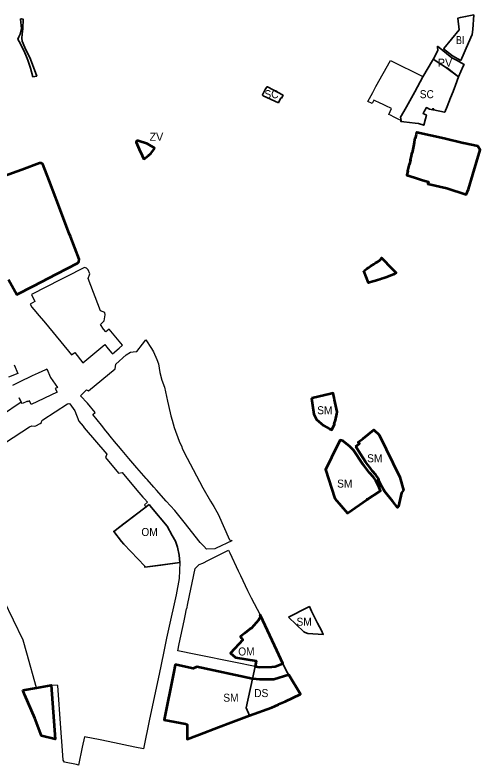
# Model space of a CAD drawing. Extents: x -650276 to -642489, y -1074311 to -1066658.
# Drawn here: x -647428 to -646731, y -1071572 to -1070448 of the extents above; entities that cross this region are included whole.
import ezdxf

# ---------------------------------------------------------------- set-up
doc = ezdxf.new("R2010")
doc.units = 0
doc.header["$LTSCALE"] = 4.8
doc.header["$PDMODE"] = 32
doc.header["$PDSIZE"] = 2.4
for name, color, linetype, lineweight in [('12', 7, 'Continuous', 35), ('15', 7, 'Continuous', 35), ('17', 7, 'Continuous', 35), ('18', 7, 'Continuous', 35), ('2', 7, 'Continuous', 35), ('24', 7, 'Continuous', 35), ('40', 7, 'Continuous', 35), ('60', 7, 'Continuous', 53), ('61', 7, 'Continuous', 25)]:
    doc.layers.add(name, color=color, linetype=linetype, lineweight=lineweight)
doc.layers.add('62', color=7, linetype='Continuous')
doc.layers.add('63', color=7, linetype='Continuous')

msp = doc.modelspace()

# ---------------------------------------------------------------- linework, layer by layer
at = {"layer": '12'}
for points in [[(-647226.895, -1071181.511), (-647280.14, -1071221.92), (-647268.52, -1071236.78), (-647265.15, -1071241.1), (-647233.34, -1071274.07), (-647233.64, -1071275.42), (-647218.75, -1071273.32), (-647181.12, -1071268.66), (-647181.99, -1071257.66), (-647184.58, -1071245.67), (-647187.68, -1071236.74), (-647192.29, -1071228.1), (-647199.82, -1071213.98), (-647223.46, -1071185.83)], [(-647056.48, -1071355.32), (-647060.6, -1071346.87), (-647060.22, -1071349.87), (-647061.4, -1071352.51), (-647062.78, -1071354.77), (-647073.68, -1071366.75), (-647075.25, -1071368.01), (-647083.48, -1071374.62), (-647090.04, -1071379.44), (-647088.57, -1071381.97), (-647086.45, -1071384.59), (-647105.2, -1071404.54), (-647097.5, -1071410.96), (-647066.35, -1071415.79), (-647068.162, -1071424.298), (-647061.23, -1071425.434), (-647043.137, -1071424.978), (-647038.119, -1071424.37), (-647026.472, -1071419.614), (-647035.47, -1071400.31)]]:
    msp.add_lwpolyline(points, close=True, dxfattribs=at)
at = {"layer": '15'}
msp.add_lwpolyline([(-647404.96, -1070527.57), (-647401.35, -1070540.59), (-647395.75, -1070539.47), (-647404.879, -1070514.114), (-647413.552, -1070496.671), (-647417.297, -1070487.185), (-647418.038, -1070482.516), (-647417.482, -1070476.846), (-647416.37, -1070468.064), (-647416.148, -1070454.055), (-647418.49, -1070453.76), (-647420.13, -1070454.78), (-647420.22, -1070454.02), (-647418.41, -1070468.21), (-647420.74, -1070476.57), (-647422.285, -1070480.931), (-647424.226, -1070484.029), (-647422.19, -1070487.75), (-647414.6, -1070502.16), (-647410.86, -1070510.68), (-647408.82, -1070515.49)], close=True, dxfattribs=at)
for points in [[(-646794.59, -1070494.62), (-646794.53, -1070495.7), (-646793.75, -1070501.26), (-646800.6, -1070513.43), (-646800.94, -1070514.04)], [(-646755.84, -1070524.5), (-646754.52, -1070522.08), (-646765.96, -1070515.75), (-646770.95, -1070512.94), (-646773, -1070511.96), (-646794.59, -1070494.62)], [(-646800.94, -1070514.04), (-646788, -1070522.49), (-646782.63, -1070526.02)], [(-646782.63, -1070526.02), (-646779.68, -1070527.87), (-646762.71, -1070540.85), (-646755.84, -1070524.5)], [(-647072.11, -1071442.6), (-647060.812, -1071444.006), (-647040.089, -1071443.76), (-647017.7, -1071436.79), (-647020.52, -1071432.42), (-647026.472, -1071419.614)], [(-647068.162, -1071424.298), (-647068.162, -1071424.298), (-647072.11, -1071442.6)], [(-647026.472, -1071419.614), (-647038.119, -1071424.37), (-647043.137, -1071424.978), (-647061.23, -1071425.434), (-647068.162, -1071424.298)]]:
    msp.add_lwpolyline(points, dxfattribs=at)
msp.add_point((-647072.11, -1071442.6), dxfattribs=at)
at = {"layer": '17'}
for points in [[(-646802.19, -1070516.26), (-646816.42, -1070540.49), (-646828.45, -1070562.89), (-646841.16, -1070585.79), (-646844.76, -1070592.54), (-646849.72, -1070600.98), (-646848.99, -1070606.28), (-646849.59, -1070607.4), (-646844.96, -1070607.98), (-646827.88, -1070610.12), (-646822.99, -1070610.51), (-646815.05, -1070613.14), (-646812.5, -1070603.78), (-646811.5, -1070600.29), (-646810.82, -1070598.23), (-646816.11, -1070595.8), (-646814.52, -1070592.78), (-646811.06, -1070586.67), (-646806.41, -1070589), (-646802.06, -1070589.93), (-646801.73, -1070588.37), (-646800.13, -1070588.71), (-646800.47, -1070590.28), (-646784.18, -1070593.76), (-646784, -1070593.34), (-646783.59, -1070593.52), (-646779.9, -1070584.92), (-646774.91, -1070571.88), (-646771.17, -1070562.7), (-646767.63, -1070553.09), (-646762.71, -1070540.85), (-646782.63, -1070526.02), (-646788, -1070522.49), (-646800.94, -1070514.04)], [(-647033.01, -1070579.83), (-647029.44, -1070572.13), (-647028.52, -1070572.63), (-647026.14, -1070568.26), (-647049.52, -1070555.64), (-647050.37, -1070555.74), (-647051.14, -1070556.59), (-647052.77, -1070559.7), (-647056.79, -1070567.41), (-647056.8, -1070568.32), (-647055.79, -1070569.07)]]:
    msp.add_lwpolyline(points, close=True, dxfattribs=at)
at = {"layer": '18'}
for points in [[(-646983.66, -1071022.3), (-646982.08, -1071032.76), (-646979.75, -1071046.19), (-646976.03, -1071054.29), (-646965.69, -1071063.05), (-646956.66, -1071067.91), (-646952.75, -1071069.62), (-646948.83, -1071061.12), (-646949.48, -1071060.79), (-646947.41, -1071054.95), (-646945.38, -1071045.82), (-646944.88, -1071042.78), (-646948.89, -1071024.84), (-646949.39, -1071021.83), (-646951.06, -1071014.78), (-646955.09, -1071015.67)], [(-646881.89, -1071077.03), (-646890.12, -1071069.67), (-646913.49, -1071088.22), (-646911.58, -1071089.9), (-646917.04, -1071094.75), (-646910.53, -1071105.18), (-646902.62, -1071117.58), (-646895.56, -1071126.84), (-646892.339, -1071131.481), (-646886.78, -1071137.25), (-646882.37, -1071143.39), (-646883.63, -1071144.15), (-646873.89, -1071161.58), (-646861.58, -1071177.05), (-646854.49, -1071185.87), (-646852.86, -1071183.98), (-646848.58, -1071163.95), (-646845.39, -1071159.98), (-646850.93, -1071140.54)], [(-646951.831, -1071107.765), (-646955.138, -1071114.466), (-646962.471, -1071129.325), (-646948.286, -1071172.534), (-646929.64, -1071194.58), (-646899.85, -1071173.89), (-646881.68, -1071161.83), (-646879.91, -1071161.24), (-646881.97, -1071155.84), (-646887.07, -1071145.66), (-646890.59, -1071140.39), (-646896.62, -1071133.93), (-646904.64, -1071123.54), (-646906.72, -1071120.46), (-646920.54, -1071099.98), (-646925.88, -1071094.68), (-646936.51, -1071086.33), (-646940.67, -1071085.15), (-646940.67, -1071085.15)], [(-647017.93, -1071350.33), (-647013.15, -1071348.01), (-647004.02, -1071343.32), (-647003.37, -1071342.99), (-646993.38, -1071337.85), (-646986.69, -1071334.53), (-646983.33, -1071341.44), (-646977.95, -1071352.38), (-646974.28, -1071359.48), (-646968.63, -1071370.46), (-646965.74, -1071376.18), (-646988.77, -1071374.77), (-646992.95, -1071373.61), (-646994.85, -1071372.49)], [(-647072.11, -1071442.6), (-647155.36, -1071425), (-647161.2, -1071427.33), (-647185.99, -1071421.98), (-647187.85, -1071421.58), (-647190.4, -1071434.75), (-647204.42, -1071504.1), (-647172.74, -1071510.15), (-647170.01, -1071511.22), (-647170.18, -1071532.22), (-647170.23, -1071533.44), (-647155.58, -1071527.62), (-647151.28, -1071525.99), (-647123.17, -1071515.01), (-647104.47, -1071508.08), (-647076.46, -1071497.69), (-647081.488, -1071486.251)]]:
    msp.add_lwpolyline(points, close=True, dxfattribs=at)
msp.add_point((-646899.85, -1071173.89), dxfattribs=at)
at = {"layer": '2'}
for points in [[(-646739.74, -1070447.98), (-646752.29, -1070450.28), (-646760.03, -1070451.56), (-646763.94, -1070452.95), (-646761.8, -1070470.4), (-646785.15, -1070498.05), (-646785.5, -1070498.47)], [(-646759.42, -1070516.37), (-646747.89, -1070489.87), (-646742.37, -1070477.2), (-646741.33, -1070469.79), (-646739.74, -1070447.98)], [(-646785.5, -1070498.47), (-646771.9, -1070509.4), (-646759.42, -1070516.37)]]:
    msp.add_lwpolyline(points, dxfattribs=at)
at = {"layer": '24'}
msp.add_line((-647081.488, -1071486.251), (-647076.46, -1071497.69), dxfattribs=at)
for points in [[(-647017.7, -1071436.79), (-647040.089, -1071443.76), (-647060.812, -1071444.006), (-647072.11, -1071442.6), (-647081.488, -1071486.251)], [(-647076.46, -1071497.69), (-647042.78, -1071485.76), (-647022.81, -1071476.61), (-646999.77, -1071465.81), (-647017.7, -1071436.79)]]:
    msp.add_lwpolyline(points, dxfattribs=at)
at = {"layer": '40'}
for points in [[(-647218.44, -1070647.43), (-647229.34, -1070640.91), (-647243.28, -1070636.43), (-647245.6, -1070636.4), (-647246.49, -1070638.53), (-647241.89, -1070648.94)], [(-647241.89, -1070648.94), (-647237.61, -1070658.33), (-647235.02, -1070664.1), (-647227.76, -1070658.33)], [(-647227.76, -1070658.33), (-647224.57, -1070655.48), (-647224.37, -1070655.59), (-647218.44, -1070647.43)]]:
    msp.add_lwpolyline(points, dxfattribs=at)
at = {"layer": '60'}
msp.add_line((-647235.02, -1070664.1), (-647227.76, -1070658.33), dxfattribs=at)
for points in [[(-646825.54, -1070624.03), (-646826.12, -1070623.9), (-646826.45, -1070627.3), (-646827.98, -1070632.83), (-646828.22, -1070632.77), (-646829.55, -1070638.78), (-646829.55, -1070638.78), (-646829.3, -1070638.83), (-646830.51, -1070644.3), (-646830.26, -1070644.35), (-646832.46, -1070654.31), (-646832.7, -1070654.26), (-646834.27, -1070661.39), (-646834.27, -1070661.39), (-646834.4, -1070661.35), (-646835.23, -1070665.08), (-646835.1, -1070665.12), (-646836.6, -1070671.54), (-646836.6, -1070671.54), (-646836.87, -1070671.46), (-646839.27, -1070681.62), (-646838.96, -1070681.72), (-646840.36, -1070687.86), (-646828.7, -1070691.73), (-646816.84, -1070695.43), (-646808.09, -1070698.19), (-646808.76, -1070701.11), (-646780.44, -1070707.59), (-646751.23, -1070717), (-646748.04, -1070709.23), (-646741.52, -1070687.22), (-646730.66, -1070650.07), (-646734.18, -1070644.6), (-646755.21, -1070639.87), (-646755.84, -1070639.88), (-646784.62, -1070633.19)], [(-646904.8, -1070831.23), (-646900.57, -1070828.42), (-646900.09, -1070828.1), (-646897.34, -1070826.28), (-646894.84, -1070824.62), (-646892.34, -1070822.96), (-646889.85, -1070821.3), (-646887.3, -1070819.61), (-646884.68, -1070817.87), (-646882.18, -1070816.21), (-646878.66, -1070812.72), (-646878.61, -1070812.14), (-646862.56, -1070828.29), (-646856.41, -1070834.13), (-646860.55, -1070836.71), (-646871.78, -1070841.33), (-646875.05, -1070842.32), (-646878.26, -1070843.29), (-646881.11, -1070844.21), (-646884.27, -1070845.17), (-646887.32, -1070846.14), (-646891.42, -1070847.44), (-646897.71, -1070849.39), (-646901.26, -1070840.31)], [(-646983.66, -1071022.3), (-646982.08, -1071032.76), (-646979.75, -1071046.19), (-646976.03, -1071054.29), (-646965.69, -1071063.05), (-646956.66, -1071067.91), (-646952.75, -1071069.62), (-646948.83, -1071061.12), (-646949.48, -1071060.79), (-646947.41, -1071054.95), (-646945.38, -1071045.82), (-646944.88, -1071042.78), (-646948.89, -1071024.84), (-646949.39, -1071021.83), (-646951.06, -1071014.78), (-646955.09, -1071015.67), (-646982.41, -1071022.23)], [(-646917.04, -1071094.75), (-646911.58, -1071089.9), (-646913.49, -1071088.22), (-646906.17, -1071082.72), (-646890.12, -1071069.67), (-646881.89, -1071077.03), (-646850.93, -1071140.54), (-646845.39, -1071159.98), (-646848.58, -1071163.95), (-646852.86, -1071183.98), (-646854.49, -1071185.87), (-646861.58, -1071177.05), (-646873.89, -1071161.58), (-646877.226, -1071155.611), (-646883.63, -1071144.15), (-646882.37, -1071143.39), (-646886.78, -1071137.25), (-646892.11, -1071131.81), (-646895.56, -1071126.84), (-646902.62, -1071117.58), (-646910.53, -1071105.18)], [(-646951.831, -1071107.765), (-646955.138, -1071114.466), (-646962.471, -1071129.325), (-646948.286, -1071172.534), (-646929.64, -1071194.58), (-646899.85, -1071173.89), (-646881.68, -1071161.83), (-646879.91, -1071161.24), (-646881.97, -1071155.84), (-646887.07, -1071145.66), (-646890.59, -1071140.39), (-646896.62, -1071133.93), (-646904.64, -1071123.54), (-646906.72, -1071120.46), (-646920.54, -1071099.98), (-646925.88, -1071094.68), (-646936.51, -1071086.33), (-646940.67, -1071085.15)], [(-647056.48, -1071355.32), (-647060.6, -1071346.87), (-647060.22, -1071349.87), (-647061.4, -1071352.51), (-647062.78, -1071354.77), (-647073.68, -1071366.75), (-647075.25, -1071368.01), (-647083.48, -1071374.62), (-647090.04, -1071379.44), (-647088.57, -1071381.97), (-647086.45, -1071384.59), (-647105.2, -1071404.54), (-647097.5, -1071410.96), (-647066.35, -1071415.79), (-647068.162, -1071424.298), (-647061.23, -1071425.434), (-647043.137, -1071424.978), (-647038.119, -1071424.37), (-647026.472, -1071419.614), (-647035.47, -1071400.31)], [(-647072.11, -1071442.6), (-647155.36, -1071425), (-647161.2, -1071427.33), (-647185.99, -1071421.98), (-647187.85, -1071421.58), (-647190.4, -1071434.75), (-647204.42, -1071504.1), (-647172.74, -1071510.15), (-647170.01, -1071511.22), (-647170.18, -1071532.22), (-647170.23, -1071533.44), (-647155.58, -1071527.62), (-647151.28, -1071525.99), (-647123.17, -1071515.01), (-647104.47, -1071508.08), (-647076.46, -1071497.69), (-647042.78, -1071485.76), (-647038.62, -1071483.74), (-647033.09, -1071481.06), (-647032.73, -1071480.88), (-647022.81, -1071476.61), (-646999.77, -1071465.81), (-647017.7, -1071436.79), (-647040.089, -1071443.76), (-647060.812, -1071444.006)], [(-647416.42, -1071460.03), (-647396.02, -1071456.32), (-647374.2, -1071452.36), (-647368.26, -1071532.99), (-647388.29, -1071528.41), (-647398.64, -1071501.96), (-647413.54, -1071467.53)]]:
    msp.add_lwpolyline(points, close=True, dxfattribs=at)
for points in [[(-647218.44, -1070647.43), (-647229.34, -1070640.91), (-647243.28, -1070636.43), (-647245.6, -1070636.4), (-647246.49, -1070638.53), (-647241.89, -1070648.94)], [(-647241.89, -1070648.94), (-647237.61, -1070658.33), (-647235.02, -1070664.1)], [(-647227.76, -1070658.33), (-647224.57, -1070655.48), (-647224.37, -1070655.59), (-647218.44, -1070647.43)], [(-647437.79, -1070844.12), (-647425.58, -1070866.7), (-647401.15, -1070854.25), (-647365.48, -1070835.85), (-647334.27, -1070819.86), (-647332.51, -1070817.97), (-647332.25, -1070813.72), (-647345.18, -1070779.89), (-647346.96, -1070775.41), (-647365.94, -1070725.08), (-647367.67, -1070720.73), (-647377.04, -1070696.22), (-647386.39, -1070671.74), (-647388.31, -1070669.95), (-647391.74, -1070670.16), (-647418.28, -1070679.89), (-647444.78, -1070689.6)]]:
    msp.add_lwpolyline(points, dxfattribs=at)
at = {"layer": '61'}
for points in [[(-646867.54, -1070597.11), (-646863.26, -1070588.3), (-646872.19, -1070583.97), (-646876.02, -1070582.12), (-646877.88, -1070581.22), (-646879.541, -1070580.417), (-646889.9, -1070575.41), (-646892.4, -1070580.64), (-646899.2, -1070577.61), (-646891.65, -1070564.15), (-646886.72, -1070555.37), (-646864.73, -1070516.2), (-646816.66, -1070540.37), (-646816.42, -1070540.49), (-646828.45, -1070562.89), (-646838.95, -1070581.53), (-646841.16, -1070585.79), (-646844.76, -1070592.54), (-646849.72, -1070600.98), (-646849.72, -1070600.98), (-646848.99, -1070606.28), (-646852.3, -1070604.63), (-646859.48, -1070601.1), (-646865.02, -1070598.34)], [(-647299.98, -1070891.49), (-647318.68, -1070842.72), (-647316.06, -1070835.75), (-647318.44, -1070829.76), (-647321.01, -1070827.14), (-647324.15, -1070826.29), (-647331.02, -1070829.74), (-647345.71, -1070837.13), (-647359.71, -1070844.27), (-647403.51, -1070866.6), (-647398.52, -1070877.49), (-647405.34, -1070881.23), (-647402.82, -1070885.66), (-647396.9, -1070892.8), (-647394.88, -1070895.23), (-647382.57, -1070910.05), (-647343.34, -1070957.27), (-647338.57, -1070953.63), (-647326.51, -1070969.42), (-647293.51, -1070942.01), (-647290.28, -1070945.89), (-647283.54, -1070954.02), (-647282.46, -1070955.31), (-647281.97, -1070955.9), (-647271.95, -1070947.47), (-647266.79, -1070942.95), (-647286.92, -1070918.59), (-647292.14, -1070922.88), (-647295.69, -1070918.55), (-647300.07, -1070911.99), (-647294.73, -1070906.32), (-647293.09, -1070897.18), (-647293.7, -1070893.99)], [(-647223.65, -1070947.55), (-647220.46, -1070952.68), (-647215.29, -1070964.36), (-647213.23, -1070970.92), (-647210.97, -1070983.56), (-647207.77, -1070995.03), (-647204.055, -1071005.609), (-647203.96, -1071005.88), (-647199.63, -1071026.94), (-647195.64, -1071044.04), (-647194.61, -1071048.68), (-647192.72, -1071055.27), (-647189.68, -1071065.99), (-647181.99, -1071086.74), (-647178.11, -1071095.31), (-647177.46, -1071097.42), (-647170.18, -1071112.08), (-647161.13, -1071129.3), (-647146.28, -1071156.35), (-647135.21, -1071176.44), (-647130.1, -1071184.33), (-647125.44, -1071192.58), (-647123.7, -1071196.19), (-647106.7, -1071234.45), (-647104.17, -1071235.6), (-647103.31, -1071235.22), (-647102.97, -1071235.92), (-647126.477, -1071247.083), (-647128.45, -1071248.02), (-647141.14, -1071248.62), (-647145.16, -1071243.92), (-647150.32, -1071238.51), (-647169.11, -1071214.8), (-647172.63, -1071210.63), (-647188.68, -1071190.78), (-647201.42, -1071176.7), (-647215.86, -1071160.1), (-647219.82, -1071155.78), (-647229.97, -1071144.1), (-647231.32, -1071142.57), (-647238.29, -1071134.66), (-647245.31, -1071126.75), (-647257.41, -1071112.55), (-647267.64, -1071100.44), (-647272.93, -1071094.24), (-647278.77, -1071087.15), (-647285.53, -1071079.39), (-647289.1, -1071074.88), (-647292.21, -1071071.21), (-647298.74, -1071062.85), (-647311.58, -1071046.44), (-647308, -1071043.56), (-647319.46, -1071029.7), (-647329.84, -1071018.95), (-647320.83, -1071009.87), (-647317.99, -1071010.98), (-647278.2, -1070978.19), (-647277.18, -1070971.26), (-647261.35, -1070957.45), (-647255.21, -1070953.46), (-647251.11, -1070953.01), (-647245.32, -1070952.38), (-647237.16, -1070941.5), (-647232.24, -1070934.94)], [(-647093.11, -1071411.77), (-647066.35, -1071415.79), (-647068.162, -1071424.298), (-647097.427, -1071418.318), (-647157.231, -1071406.28), (-647183.816, -1071400.974), (-647181.75, -1071390.51), (-647174.73, -1071356.1), (-647173.24, -1071348.27), (-647170.96, -1071337.84), (-647170.63, -1071337.91), (-647168.91, -1071329.88), (-647157.83, -1071277.35), (-647152.09, -1071271.47), (-647146.3, -1071269.33), (-647137.84, -1071265.06), (-647130.76, -1071261.49), (-647108.16, -1071250.08), (-647106.233, -1071254.01), (-647093.39, -1071280.83), (-647090, -1071287.89), (-647079.25, -1071310.33), (-647073.98, -1071321.53), (-647060.6, -1071346.87), (-647060.22, -1071349.87), (-647061.4, -1071352.51), (-647062.78, -1071354.77), (-647073.68, -1071366.75), (-647075.25, -1071368.01), (-647083.48, -1071374.62), (-647083.48, -1071374.62), (-647090.04, -1071379.44), (-647086.45, -1071384.59), (-647105.2, -1071404.54), (-647097.5, -1071410.96)]]:
    msp.add_lwpolyline(points, close=True, dxfattribs=at)
for points in [[(-647429.44, -1070972.06), (-647424.16, -1070985.19), (-647438.05, -1070990.74)], [(-647431.74, -1071002.56), (-647413.35, -1070993.67), (-647410.26, -1070992.23), (-647407.22, -1070990.81), (-647401.93, -1070988.34), (-647392.83, -1070984.14), (-647382.05, -1070979.01), (-647380.69, -1070978.37), (-647374.95, -1070991.15), (-647364.66, -1071006.25), (-647367.88, -1071007.78), (-647365.21, -1071013.19), (-647403.85, -1071031.66), (-647406.65, -1071026.24), (-647409.36, -1071027.52), (-647409.68, -1071026.85), (-647411.52, -1071027.64), (-647415.84, -1071029.49), (-647417.76, -1071030.31), (-647418.88, -1071028.01), (-647421.89, -1071021.82), (-647418.88, -1071028.01), (-647448.32, -1071048.39)], [(-647442.36, -1071088.82), (-647406.52, -1071065.05), (-647403.15, -1071063.6), (-647399.31, -1071064.09), (-647397.17, -1071063.56), (-647390.72, -1071059.94), (-647388.51, -1071058.82), (-647387.82, -1071056.14), (-647386.3, -1071054.58), (-647349.67, -1071030.64), (-647347.66, -1071030.16), (-647345.94, -1071030.88), (-647338.47, -1071040.94), (-647332.55, -1071056.58), (-647326.18, -1071064.18), (-647324.46, -1071066.41), (-647290.44, -1071106.08), (-647292.31, -1071111.16), (-647272.8, -1071134.42), (-647267.4, -1071133.54), (-647245.43, -1071159.88), (-647239.35, -1071166.98), (-647236.41, -1071170.41), (-647234.12, -1071172.97), (-647229.71, -1071178.23), (-647234.22, -1071182.02), (-647233.57, -1071182.82), (-647231.69, -1071185.15), (-647262.35, -1071208.42), (-647263.8, -1071209.52), (-647278.04, -1071220.33), (-647280.14, -1071221.92), (-647268.52, -1071236.78), (-647265.15, -1071241.1), (-647233.34, -1071274.07), (-647233.64, -1071275.42), (-647209.66, -1071272.22), (-647181.12, -1071268.66), (-647181.79, -1071292.49), (-647186.6, -1071316.98), (-647197.87, -1071368.22), (-647200.76, -1071382.02), (-647202.98, -1071391.98), (-647205.52, -1071404.32), (-647212.07, -1071435.71), (-647226.296, -1071503.249), (-647235.71, -1071547.94), (-647248.51, -1071545.3), (-647265.23, -1071541.68), (-647278.94, -1071538.77), (-647300.51, -1071534.33), (-647324.04, -1071529.54), (-647327.31, -1071545.25), (-647332.86, -1071571.94), (-647335.88, -1071571.31), (-647353.95, -1071567.53), (-647356.2, -1071564.75), (-647357.15, -1071550.44), (-647359.38, -1071516.88), (-647363.86, -1071452.66), (-647374.2, -1071452.36), (-647396.02, -1071456.32), (-647410.56, -1071404.35), (-647415.97, -1071385.01), (-647445, -1071324.99)]]:
    msp.add_lwpolyline(points, dxfattribs=at)

# ---------------------------------------------------------------- texts
at = {"layer": '62'}
for s, width, p in [('BI', 0.85, (-646766.828, -1070491.569)), ('SC', 0.95, (-647054.06, -1070572.645)), ('SC', 0.95, (-646821.06, -1070572.645)), ('SM', 0.95, (-646974.938, -1071046.245)), ('SM', 0.95, (-646899.938, -1071118.245)), ('OM', 0.95, (-647238.703, -1071228.756)), ('SM', 0.95, (-647005.938, -1071363.245)), ('OM', 0.95, (-647093.38, -1071407.817)), ('DS', 0.95, (-647069.386, -1071470.148)), ('SM', 0.95, (-647115.735, -1071477.109))]:
    msp.add_text(s, height=12, dxfattribs=dict(at, width=width)).set_placement(p)
msp.add_text('PV', height=12, dxfattribs=at).set_placement((-646793.831, -1070525.433))
at = {"layer": '63'}
msp.add_text('ZV', height=12, dxfattribs=at).set_placement((-647226.398, -1070636.507))
at = {"layer": '63', "width": 0.95}
msp.add_text('SM', height=12, dxfattribs=at).set_placement((-646944.938, -1071156.245))

doc.saveas('drawing.dxf')
